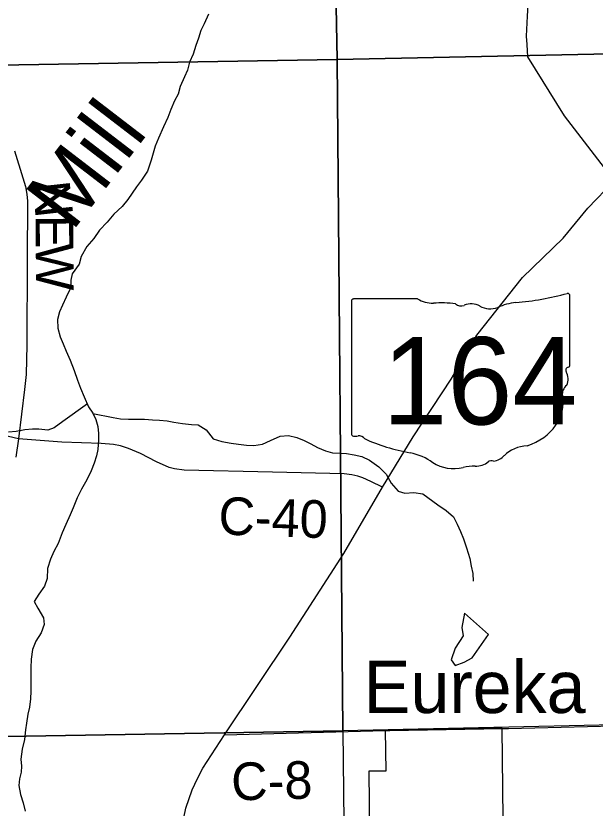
# Model space of a CAD drawing. Extents: x 0 to 36.9, y 0 to 22.
# Drawn here: x 6.733 to 7.606, y 15.386 to 16.582 of the extents above; entities that cross this region are included whole.
import ezdxf

# ---------------------------------------------------------------- set-up
doc = ezdxf.new("R2010")
doc.units = 0
for name, color, linetype in [('Default', 7, 'Continuous'), ('GM_X_County_Road', 7, 'Continuous'), ('GM_X_County_Road_Text', 7, 'Continuous'), ('GM_X_Major_River', 7, 'Continuous'), ('GM_X_Major_River_Text', 7, 'Continuous'), ('GM_X_Minor_Lake', 7, 'Continuous'), ('GM_X_Minor_River', 7, 'Continuous'), ('GM_X_Section', 7, 'Continuous'), ('GM_X_State_Location', 7, 'Continuous'), ('GM_X_State_Route', 7, 'Continuous'), ('GM_X_State_Shield', 7, 'Continuous'), ('GM_X_Township_Road', 7, 'Continuous'), ('GM_X_Unincorporated_Text', 7, 'Continuous')]:
    doc.layers.add(name, color=color, linetype=linetype)

msp = doc.modelspace()

# ---------------------------------------------------------------- linework, layer by layer
at = {"layer": 'Default'}
msp.add_lwpolyline([(7.4716, 15.0059), (7.4664, 15.5064), (7.2897, 15.5035), (7.2905, 15.4418), (7.2649, 15.4415), (7.2666, 15.2945)], dxfattribs=at)
at = {"layer": 'GM_X_County_Road'}
msp.add_line((7.4756, 15.5061), (7.7254, 15.5123), dxfattribs=at)
for points in [[(7.5431, 17.5191), (7.5334, 17.2126), (7.5226, 16.9418), (7.5085, 16.6619), (7.5038, 16.5816), (7.5026, 16.5512), (7.5032, 16.5386), (7.5044, 16.52), (7.56, 16.4312), (7.6351, 16.3326)], [(6.7306, 16.3779), (6.7433, 16.3374), (6.747, 16.3242), (6.7492, 16.3125), (6.7502, 16.3022), (6.7499, 16.2141), (6.7489, 16.0854), (6.748, 16.0404), (6.7458, 16.0176), (6.7367, 15.9435), (6.7324, 15.9156)], [(7.2856, 15.8706), (7.2683, 15.8787), (7.256, 15.8843), (7.2484, 15.887), (7.2392, 15.8892), (7.228, 15.8907), (7.1198, 15.8931), (6.9863, 15.8961), (6.9719, 15.898), (6.9639, 15.8999), (6.9448, 15.9086), (6.9205, 15.9213), (6.9023, 15.929), (6.8903, 15.9328), (6.8798, 15.9347), (6.8612, 15.9365), (6.802, 15.9385), (6.7367, 15.9435)], [(7.0471, 15.4964), (7.2899, 15.503), (7.2969, 15.5031)], [(7.2969, 15.5031), (7.4666, 15.5059), (7.4756, 15.5061)]]:
    msp.add_lwpolyline(points, dxfattribs=at)
at = {"layer": 'GM_X_Major_River'}
for points in [[(7.0232, 16.5847), (7.0166, 16.5698), (7.0118, 16.5598), (7.0083, 16.548), (7.0043, 16.5373), (7.0003, 16.5243), (6.9948, 16.512), (6.9913, 16.4998), (6.9869, 16.4899), (6.9803, 16.4753), (6.9775, 16.4635), (6.972, 16.4535), (6.9665, 16.4405), (6.9618, 16.4283), (6.9552, 16.4145), (6.9479, 16.3973), (6.9428, 16.3854), (6.9396, 16.3747), (6.9368, 16.3641), (6.9314, 16.3476), (6.9221, 16.3338), (6.9147, 16.3238), (6.9017, 16.3046)], [(6.9017, 16.3046), (6.8928, 16.2942), (6.8805, 16.2826), (6.8705, 16.2706), (6.8589, 16.2586), (6.85, 16.2459), (6.8396, 16.2336), (6.8311, 16.2187), (6.8283, 16.2072), (6.8176, 16.1926), (6.8155, 16.1827), (6.8157, 16.1717), (6.8087, 16.1571), (6.8032, 16.1449), (6.7985, 16.1349), (6.7953, 16.1235), (6.7959, 16.1102), (6.7995, 16.0974), (6.8039, 16.0868), (6.8087, 16.0755), (6.8146, 16.0619), (6.8206, 16.0465), (6.8258, 16.0318), (6.8302, 16.0197), (6.8357, 16.0069), (6.8424, 15.9918), (6.8487, 15.9821), (6.853, 15.9723), (6.8563, 15.9621), (6.8572, 15.9515), (6.8574, 15.942), (6.8561, 15.9272), (6.854, 15.9176), (6.8508, 15.9066), (6.8461, 15.8951), (6.8395, 15.8817), (6.8314, 15.8675), (6.8252, 15.8541), (6.819, 15.8392), (6.8146, 15.8285), (6.808, 15.8139), (6.8026, 15.8013), (6.7964, 15.7852), (6.7901, 15.7734), (6.7847, 15.7615), (6.7804, 15.7474), (6.7799, 15.7326), (6.7759, 15.7211), (6.7674, 15.7088), (6.76, 15.698), (6.7659, 15.6879), (6.7745, 15.6732), (6.7754, 15.663), (6.7707, 15.6504), (6.7626, 15.6381), (6.7579, 15.6255), (6.7558, 15.6106), (6.7553, 15.5974), (6.7552, 15.5852), (6.7554, 15.5738), (6.7552, 15.5624), (6.7546, 15.551), (6.753, 15.5385), (6.7509, 15.5278), (6.7485, 15.5141), (6.7471, 15.5038), (6.7455, 15.4894), (6.7423, 15.4749), (6.7399, 15.4597), (6.7409, 15.4494), (6.7407, 15.4399), (6.7382, 15.43), (6.7369, 15.4201), (6.7394, 15.4065), (6.7438, 15.3937), (6.7467, 15.3812)]]:
    msp.add_lwpolyline(points, dxfattribs=at)
at = {"layer": 'GM_X_Minor_Lake'}
for points in [[(7.4096, 15.6801), (7.4055, 15.6584), (7.4076, 15.6459), (7.3954, 15.6271), (7.3892, 15.6095), (7.3955, 15.6013), (7.409, 15.6061), (7.4211, 15.6128), (7.4455, 15.6481)], [(7.4455, 15.6481), (7.4096, 15.6801)]]:
    msp.add_lwpolyline(points, dxfattribs=at)
at = {"layer": 'GM_X_Minor_River'}
for points in [[(6.8405, 15.996), (6.8037, 15.9695), (6.7906, 15.9598), (6.7808, 15.9562), (6.7675, 15.9578), (6.7576, 15.958), (6.7462, 15.9567), (6.733, 15.9546), (6.7216, 15.9536)], [(6.8488, 15.9817), (6.8796, 15.9754), (6.8906, 15.9737), (6.9024, 15.9732), (6.9267, 15.9728), (6.9385, 15.9719), (6.9491, 15.9714), (6.9609, 15.9704), (6.9708, 15.9687), (6.9838, 15.9663), (6.9975, 15.965), (7.0077, 15.9644), (7.0196, 15.9567), (7.0301, 15.9436), (7.0435, 15.9393), (7.0576, 15.9369), (7.0686, 15.9355), (7.0804, 15.9339), (7.0918, 15.9333), (7.1047, 15.9351), (7.1167, 15.941), (7.1314, 15.9473), (7.1439, 15.9483), (7.1565, 15.9455), (7.1676, 15.9407), (7.1776, 15.9356), (7.1879, 15.9301), (7.1998, 15.925), (7.2105, 15.9222), (7.2219, 15.9216), (7.2314, 15.921), (7.2428, 15.9193), (7.2546, 15.9165), (7.2661, 15.911), (7.2804, 15.901), (7.2912, 15.8898), (7.2986, 15.8763), (7.3091, 15.8643), (7.3194, 15.8615), (7.3331, 15.8621), (7.3468, 15.8601), (7.3691, 15.8438), (7.3818, 15.8353), (7.3926, 15.8256), (7.3981, 15.8147), (7.4032, 15.8034), (7.408, 15.7925), (7.4124, 15.7789), (7.4176, 15.7627), (7.4197, 15.7509), (7.4218, 15.74), (7.4224, 15.7286)]]:
    msp.add_lwpolyline(points, dxfattribs=at)
at = {"layer": 'GM_X_Section'}
for points in [[(8.1912, 17.5487), (8.21, 16.5368), (7.2171, 16.5161), (7.1983, 17.5272)], [(7.1983, 17.5272), (7.2171, 16.5161), (6.226, 16.4996), (6.2201, 17.5106)], [(7.2171, 16.5161), (8.21, 16.5368), (8.2269, 15.5248), (7.2257, 15.5025)], [(6.226, 16.4996), (7.2171, 16.5161), (7.2257, 15.5025), (6.2395, 15.4861)], [(6.2395, 15.4861), (7.2257, 15.5025), (7.2369, 14.4927), (6.2525, 14.4815)]]:
    msp.add_lwpolyline(points, close=True, dxfattribs=at)
at = {"layer": 'GM_X_State_Route'}
for points in [[(7.0471, 15.4964), (7.1457, 15.6437), (7.2273, 15.7704), (7.2856, 15.8706), (7.332, 15.9464), (7.3892, 16.0334), (7.428, 16.0996), (7.4971, 16.1868), (7.5585, 16.2465), (7.5956, 16.2915), (7.6351, 16.3326), (7.7529, 16.4322), (7.8671, 16.5247), (7.9067, 16.5599), (7.9185, 16.5733), (7.9403, 16.6034)], [(6.9191, 15.036), (6.9246, 15.0599), (6.9406, 15.1397), (6.9598, 15.2359), (6.975, 15.3179), (6.9892, 15.386), (6.9984, 15.4134), (7.0066, 15.4307), (7.0148, 15.4464), (7.0471, 15.4964)]]:
    msp.add_lwpolyline(points, dxfattribs=at)
at = {"layer": 'GM_X_State_Shield'}
for p, q in [((7.239, 16.151), (7.239, 15.9509)), ((7.3387, 16.1545), (7.2422, 16.1545)), ((7.5685, 16.0547), (7.5685, 16.1594)), ((7.5685, 16.0548), (7.5685, 16.0547))]:
    msp.add_line(p, q, dxfattribs=at)
for centre, major_axis, start_param, end_param in [((7.4511, 16.4273), (0.3495, 0), 4.814394, 5.042369), ((7.5649, 16.1599), (0.00367, 0), 6.141152, 7.989035), ((7.2427, 16.1514), (0.00382, 0), 1.712693, 3.28349), ((7.3617, 16.1777), (0.037, 0), 4.042523, 4.731795), ((7.374, 16.0421), (0.133, 0), 1.404758, 1.657858), ((7.4199, 16.1294), (0.0222, 0), 0.950623, 2.079405), ((7.4957, 16.0933), (0.0703, 0), 1.699011, 2.107814), ((7.4042, 16.1525), (0.0107, 0), 3.836095, 5.185415), ((7.4485, 16.1611), (0.0267, 0), 4.081561, 5.145723), ((7.5646, 16.0543), (0.00393, 0), 5.05454, 6.418171), ((7.5677, 16.0471), (0.00568, 0), 1.883978, 3.671073), ((7.5316, 16.0338), (0.0341, 0), 5.934695, 6.695948), ((7.5817, 16.0109), (0.0248, 0), 2.387724, 3.262537), ((7.4707, 15.9976), (0.0874, 0), 5.101752, 6.440018), ((7.2428, 15.9505), (0.00385, 0), 3.00124, 4.508301), ((7.2434, 15.9709), (0.0294, 0), 4.665946, 4.897461), ((7.2494, 15.9394), (0.0106, 0), 0.519207, 1.627899), ((7.3832, 16.1192), (0.2524, 0), 4.195997, 4.488961), ((7.5076, 15.8947), (0.0479, 0), 1.647645, 2.488434), ((7.3079, 15.861), (0.079, 0), 0.823519, 1.323587), ((7.426, 15.9234), (0.0267, 0), 4.691044, 5.507374), ((7.4501, 15.904), (0.00752, 0), 1.147584, 2.315152), ((7.4469, 15.9315), (0.0282, 0), 4.937069, 5.64225), ((7.3934, 15.9384), (0.0501, 0), 4.026481, 4.996735), ((7.4223, 15.8692), (0.0412, 0), 1.495662, 1.94098)]:
    msp.add_ellipse(centre, major_axis=major_axis, ratio=0.8, start_param=start_param, end_param=end_param, dxfattribs=at)
at = {"layer": 'GM_X_Township_Road'}
msp.add_lwpolyline([(6.7367, 15.9435), (6.6869, 15.9549), (6.6479, 15.9633), (6.6132, 15.9686), (6.5852, 15.9717), (6.4543, 15.9825), (6.3674, 15.9854), (6.3322, 15.9862), (6.3229, 15.9877), (6.311, 15.9908), (6.2601, 16.0082), (6.245, 16.0126), (6.2347, 16.0153), (6.2272, 16.0163), (6.2122, 16.0179), (6.1815, 16.017), (6.1284, 16.0168), (5.8776, 16.0105), (5.831, 16.0102), (5.792, 16.0074), (5.7555, 16.0009), (5.7307, 15.9951)], dxfattribs=at)

# ---------------------------------------------------------------- texts
at = {"layer": 'GM_X_County_Road_Text'}
for s, height, rotation, p in [('N', 0.0568, 276.3332, (6.7568, 16.3294)), ('E', 0.0568, 270.5529, (6.7622, 16.2813)), ('W', 0.0568, 270.332, (6.7626, 16.2388)), ('C-40', 0.05682, 357.9421, (7.0375, 15.7991)), ('C-8', 0.05682, 1.375, (7.0581, 15.3974))]:
    msp.add_text(s, height=height, rotation=rotation, dxfattribs=at).set_placement(p)
at = {"layer": 'GM_X_Major_River_Text'}
msp.add_text('Mill', height=0.09474, rotation=52.4738, dxfattribs=at).set_placement((6.8173, 16.2547))
at = {"layer": 'GM_X_State_Location'}
for s, p in [('s', (7.4001, 16.0377)), ('r', (7.4, 16.0377))]:
    msp.add_text(s, height=0.000189, dxfattribs=at).set_placement(p)
msp.add_text('164', height=0.000189, rotation=0, dxfattribs=at).set_placement((7.3332, 16.0239))
at = {"layer": 'GM_X_State_Shield'}
msp.add_text('164', height=0.13184, dxfattribs=at).set_placement((7.2855, 15.965))
at = {"layer": 'GM_X_Unincorporated_Text'}
msp.add_text('Eureka', height=0.07898, rotation=0, dxfattribs=at).set_placement((7.2574, 15.5294))

doc.saveas('drawing.dxf')
